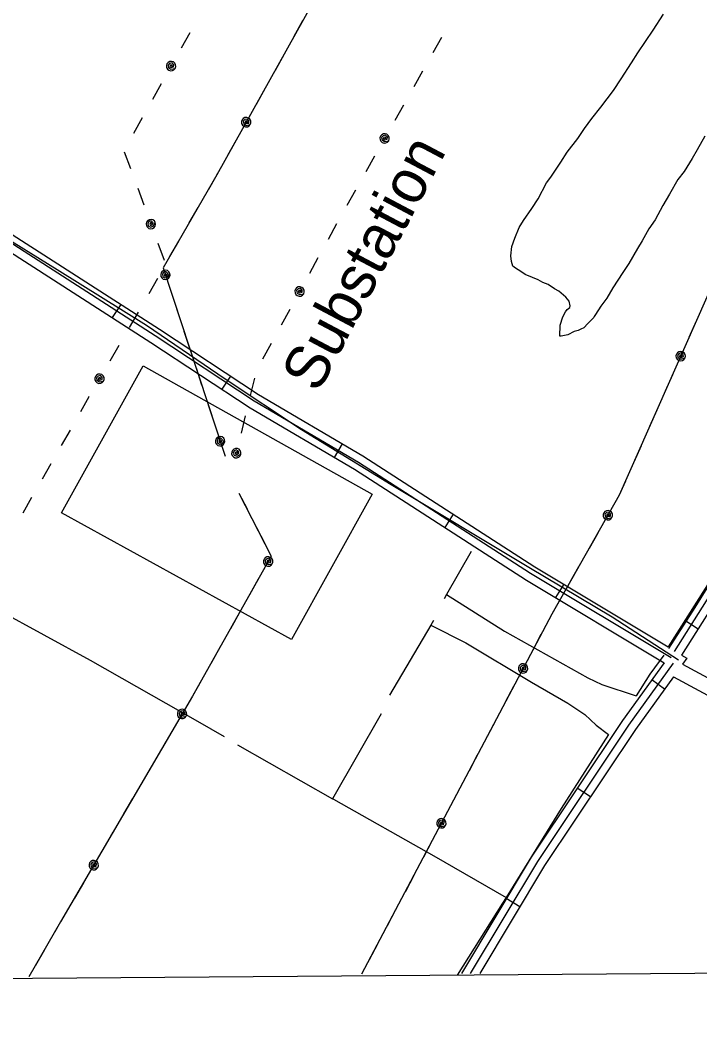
# Model space of a CAD drawing. Extents: x 3535183 to 3573198, y 534952 to 560562.
# Drawn here: x 3551055 to 3552352, y 540353 to 542269 of the extents above; entities that cross this region are included whole.
import ezdxf

# ---------------------------------------------------------------- set-up
doc = ezdxf.new("R2010")
doc.units = 0
for name, color, linetype in [('V-DTCH-CNTR', 7, 'Continuous'), ('V-GRID-FRAM', 7, 'Continuous'), ('V-ROAD-CNTR', 7, 'Continuous'), ('V-SITE-OTLN', 7, 'Continuous'), ('V-SITE-OTLN-IDEN', 7, 'Continuous'), ('V-SITE-VEGE', 7, 'Continuous'), ('V-TOPO-SHOR', 7, 'Continuous'), ('V-UTIL-LINE', 7, 'Continuous')]:
    doc.layers.add(name, color=color, linetype=linetype)

msp = doc.modelspace()

# ---------------------------------------------------------------- linework, layer by layer
at = {"layer": 'V-DTCH-CNTR'}
msp.add_lwpolyline([(3552311.1, 541048.4), (3552184.6, 541130.6), (3552025.6, 541225.3), (3551762.9, 541383.1), (3551592, 541487.8), (3551446.1, 541584.7), (3551296.1, 541686.9), (3551126.2, 541793.3), (3551006.3, 541866.6), (3550875.6, 541949.8), (3550831.4, 541978.4), (3550787.7, 542005.4)], dxfattribs=at)
at = {"layer": 'V-GRID-FRAM'}
msp.add_lwpolyline([(3539245.8, 558535.3), (3570887.5, 558774.6), (3571033, 540592.1), (3539375.4, 540352.7), (3539245.8, 558535.3)], dxfattribs=at)
at = {"layer": 'V-ROAD-CNTR'}
for p, q in [((3551247.2, 541727.2), (3551231, 541702)), ((3551456.7, 541590.4), (3551440.2, 541565.4)), ((3551669.7, 541461.1), (3551654.4, 541435.2)), ((3551881.3, 541326.9), (3551865, 541301.7)), ((3552092.1, 541193.4), (3552076.6, 541167.7)), ((3552348.3, 541107.8), (3552322.9, 541123.8)), ((3552316.8, 541058.1), (3552326.8, 541052.1)), ((3552326.8, 541052.1), (3552318.8, 541041.1)), ((3552284.3, 540993.2), (3552259.9, 541010.7)), ((3552142.8, 540787.7), (3552117.9, 540804.4)), ((3552008.1, 540578.1), (3551982.4, 540593.5))]:
    msp.add_line(p, q, dxfattribs=at)
for points in [[(3552303.4, 541064.8), (3552395.1, 541209.9), (3552544.5, 541444.8), (3552720.5, 541727.3), (3552881, 541989.5), (3553121.8, 542377.6), (3553307.4, 542678.3), (3553572.7, 543100.2), (3553604.9, 543138.1), (3553635.6, 543156.7), (3553696, 543171.6), (3553911.8, 543236.3), (3554010.3, 543265.9), (3554081.2, 543287.1), (3554118.3, 543299.2), (3554151.6, 543315.3), (3554177.7, 543339.4), (3554199.1, 543370.8), (3554286.1, 543503.7), (3554405.1, 543699.7), (3554441.4, 543759.2), (3554471.6, 543804.2)], [(3553451, 542934.8), (3553294.7, 542686.3), (3553109.1, 542385.5), (3552868.2, 541997.3), (3552707.7, 541735.1), (3552531.8, 541452.8), (3552382.4, 541217.9), (3552291.1, 541073.6)], [(3553475.6, 542917.6), (3553320.2, 542670.4), (3553134.6, 542369.7), (3552893.8, 541981.6), (3552733.3, 541719.4), (3552557.2, 541436.9), (3552407.8, 541201.9), (3552316.8, 541058.1)], [(3552297, 541052.6), (3552028.8, 541214), (3551700.7, 541425.3), (3551501.7, 541542.8), (3551313.1, 541667.1), (3550987.1, 541876.4), (3550822.1, 541980.5), (3550776.8, 542012.5)], [(3550806.1, 542010.2), (3550830.4, 541993), (3550995.2, 541889.1), (3551321.2, 541679.7), (3551509.7, 541555.5), (3551708.6, 541438.1), (3552036.8, 541226.7), (3552291.1, 541073.6)], [(3550789.9, 541984.9), (3550813.7, 541968), (3550979.1, 541863.8), (3551304.9, 541654.5), (3551493.8, 541530), (3551692.8, 541412.6), (3552020.9, 541201.3), (3552283.4, 541043.2)], [(3552283.4, 541043.2), (3552204, 540933.1), (3552029.8, 540672.6), (3551896.8, 540450.6)], [(3551914.4, 540450.8), (3552042.4, 540664.5), (3552216.3, 540924.5), (3552301.4, 541042.5)], [(3552318.8, 541041.1), (3552557.8, 540912), (3552832.4, 540737.6), (3552993.6, 540630.8), (3553002.8, 540628), (3553002.1, 540628), (3553002.6, 540628.5), (3553009.5, 540639.8)], [(3552301.2, 541016.6), (3552228.6, 540915.9), (3552055.1, 540656.5), (3551931.9, 540450.9)], [(3552301.2, 541016.6), (3552542.6, 540886.1), (3552816, 540712.5), (3552980.7, 540603.3), (3552999, 540597.8), (3553016.4, 540598.6), (3553027, 540610.8), (3553033.8, 540622)]]:
    msp.add_lwpolyline(points, dxfattribs=at)
at = {"layer": 'V-SITE-OTLN'}
msp.add_lwpolyline([(3551134.1, 541329.3), (3551290, 541610.2), (3551726.4, 541365.4), (3551573.1, 541087.7)], close=True, dxfattribs=at)
at = {"layer": 'V-SITE-VEGE'}
msp.add_lwpolyline([(3552361.1, 542047.7), (3552346.6, 542022.1), (3552336.7, 542005.6), (3552321.5, 541980.9), (3552309.9, 541965.4), (3552293.7, 541937.3), (3552281.1, 541915.9), (3552266.6, 541888.6), (3552254.1, 541871.4), (3552241.4, 541848.3), (3552232.4, 541833.5), (3552216.2, 541805.4), (3552204.6, 541788.2), (3552185.8, 541758.5), (3552174.1, 541738.8), (3552162.6, 541724), (3552152.7, 541707.5), (3552150, 541704.3), (3552149.1, 541701.8), (3552137.7, 541690.4), (3552130.6, 541682.2), (3552124.7, 541679.9), (3552119.5, 541677.6), (3552111.8, 541675.4), (3552099.8, 541669.1), (3552087.1, 541666.2), (3552084.5, 541666.3), (3552085.3, 541687.3), (3552090.1, 541703.2), (3552095.6, 541713.1), (3552098.3, 541717.2), (3552103.5, 541721.2), (3552104.4, 541724.5), (3552102.2, 541733), (3552095.8, 541740.9), (3552082.7, 541752.3), (3552074.5, 541756.9), (3552062.1, 541764.9), (3552052.2, 541768.7), (3552043.1, 541774.1), (3552032.3, 541778.7), (3552018.2, 541784.3), (3552010, 541789.6), (3552000.1, 541795.9), (3551995.2, 541800.3), (3551992.2, 541808.9), (3551990.9, 541819.9), (3551993.3, 541837.5), (3551998.9, 541853.3), (3552007.3, 541874), (3552015.4, 541887.2), (3552031.4, 541910.2), (3552043.1, 541928.3), (3552059.4, 541958.8), (3552067.4, 541969.5), (3552086.2, 541998.3), (3552098.7, 542017.2), (3552119, 542043.4), (3552131.6, 542062.3), (3552145.8, 542082), (3552162.6, 542103.3), (3552186.6, 542135.2), (3552201.7, 542157.4), (3552221.4, 542187.8), (3552233.1, 542206.8), (3552262.6, 542250.3), (3552282.3, 542280.8)], dxfattribs=at)
at = {"layer": 'V-TOPO-SHOR'}
msp.add_line((3551743.6, 540945.8), (3551651.2, 540784.2), dxfattribs=at)
for points in [[(3553030.6, 542245.1), (3552951.6, 542118.4), (3552873, 541993.5), (3552770.3, 541831.3), (3552650, 541641.1), (3552610.1, 541573.9), (3552562, 541499.2), (3552484.4, 541378.6), (3552341.8, 541149.2), (3552292.1, 541070.4)], [(3550478.9, 541450.4), (3550601.5, 541379.7), (3550817.6, 541254.1), (3551011.7, 541145), (3551189, 541048.7), (3551393.3, 540932.3), (3551444.2, 540902.7)], [(3551915.3, 541255.8), (3551868.5, 541173.4), (3551864.1, 541165.6)], [(3551868.5, 541173.4), (3551979, 541104), (3552138.2, 541014.5), (3552164.7, 541002.2), (3552230.4, 540980.6)], [(3551843.4, 541123.8), (3551838.4, 541115.4), (3551759.7, 540981.7)], [(3551838.4, 541115.4), (3551905, 541081.5), (3552030.8, 541006.3), (3552099.8, 540966.3), (3552132, 540945.1), (3552153.8, 540924.3), (3552177.2, 540906.9)], [(3552282.9, 541057.7), (3552256.1, 541022), (3552230.4, 540980.6)], [(3552177.2, 540906.9), (3552087.2, 540765.8), (3551982.1, 540596), (3551975.1, 540584.8), (3551889.1, 540447.3)], [(3551469.7, 540887), (3551651.2, 540784.2), (3551652.9, 540783.3), (3551844.4, 540675.1), (3551982.1, 540596)]]:
    msp.add_lwpolyline(points, dxfattribs=at)
at = {"layer": 'V-UTIL-LINE'}
for points in [[(3552208.3, 543370.1), (3551831.7, 542694), (3551430.6, 541974.5), (3551327.9, 541797.1), (3551446.1, 541437.4)], [(3552764.1, 542685.9), (3552564.5, 542186.9), (3552362.1, 541735.1), (3552197.8, 541363.1), (3552069.3, 541136.5), (3551706.5, 540449.2)], [(3551594.1, 542267.7), (3551577.5, 542238)], [(3551378.8, 542245.4), (3551362.2, 542215.7)], [(3551858.9, 542236.3), (3551842.2, 542206.7)], [(3551558, 542203), (3551541.5, 542173.3)], [(3551343.2, 542181.7), (3551346, 542181.9), (3551344.5, 542183.7), (3551341.8, 542183.4), (3551340.7, 542180.7), (3551343.5, 542178.9), (3551348.1, 542180), (3551348.4, 542184.3), (3551345, 542187.7), (3551340.5, 542186.7), (3551337.5, 542183.4), (3551338.4, 542178.6), (3551343, 542175.6), (3551351, 542177.3), (3551352.1, 542180.6), (3551351.8, 542184.1), (3551350.2, 542187.2), (3551347.6, 542189.5), (3551344.2, 542190.6), (3551340.7, 542190.3), (3551337.6, 542188.7), (3551335.3, 542186), (3551334.2, 542182.7), (3551334.5, 542179.2), (3551336.1, 542176.1), (3551338.8, 542173.8), (3551342.1, 542172.7), (3551345.6, 542173), (3551348.7, 542174.6), (3551351, 542177.3)], [(3551822.6, 542171.8), (3551805.9, 542142.2)], [(3551324.1, 542147.6), (3551307.6, 542117.9)], [(3551522, 542138.4), (3551505.4, 542108.7)], [(3551786.2, 542107.3), (3551769.6, 542077.7)], [(3551288, 542083), (3551271.5, 542053.3)], [(3551486.5, 542074.6), (3551489.3, 542074.9), (3551487.8, 542076.7), (3551485.1, 542076.3), (3551483.9, 542073.6), (3551486.8, 542071.9), (3551491.4, 542073), (3551491.7, 542077.3), (3551488.2, 542080.7), (3551483.8, 542079.7), (3551480.8, 542076.3), (3551481.7, 542071.6), (3551486.3, 542068.6), (3551494.3, 542070.3), (3551495.4, 542073.6), (3551495.1, 542077.1), (3551493.5, 542080.2), (3551490.8, 542082.5), (3551487.5, 542083.6), (3551484, 542083.3), (3551480.9, 542081.7), (3551478.6, 542079), (3551477.5, 542075.7), (3551477.8, 542072.2), (3551479.4, 542069.1), (3551482.1, 542066.8), (3551485.4, 542065.7), (3551488.9, 542066), (3551492, 542067.6), (3551494.3, 542070.3)], [(3551750.4, 542043.7), (3551753.3, 542044), (3551751.8, 542045.8), (3551749, 542045.4), (3551747.9, 542042.7), (3551750.8, 542040.9), (3551755.3, 542042.1), (3551755.7, 542046.3), (3551752.2, 542049.8), (3551747.8, 542048.8), (3551744.8, 542045.4), (3551745.6, 542040.7), (3551750.3, 542037.7), (3551758.3, 542039.3), (3551759.4, 542042.6), (3551759.1, 542046.1), (3551757.5, 542049.3), (3551754.8, 542051.6), (3551751.5, 542052.7), (3551748, 542052.4), (3551744.9, 542050.8), (3551742.6, 542048.1), (3551741.5, 542044.8), (3551741.7, 542041.3), (3551743.3, 542038.2), (3551746, 542035.9), (3551749.3, 542034.8), (3551752.8, 542035.1), (3551756, 542036.6), (3551758.3, 542039.3)], [(3551467.5, 542040.6), (3551450.9, 542010.9)], [(3551254, 542018.3), (3551265.7, 541986.3)], [(3551731.3, 542009.7), (3551714.6, 541980.1)], [(3551431.4, 541975.9), (3551430.6, 541974.5), (3551414.4, 541946.5)], [(3551279.5, 541948.8), (3551291.2, 541916.9)], [(3551695, 541945.3), (3551678.3, 541915.6)], [(3551394.4, 541911.9), (3551377.3, 541882.5)], [(3551304.6, 541880.3), (3551306.3, 541882.6), (3551304, 541882.6), (3551302.5, 541880.3), (3551303.8, 541877.7), (3551307, 541878.7), (3551309.1, 541882.9), (3551306.1, 541886), (3551301.2, 541885.6), (3551299.1, 541881.5), (3551299.7, 541877.1), (3551303.9, 541874.6), (3551309.1, 541876.2), (3551313.1, 541883.4), (3551311.3, 541886.4), (3551308.4, 541888.4), (3551305, 541889.2), (3551301.5, 541888.7), (3551298.6, 541886.9), (3551296.5, 541884), (3551295.7, 541880.6), (3551296.2, 541877.2), (3551298, 541874.2), (3551300.9, 541872.1), (3551304.3, 541871.3), (3551307.8, 541871.8), (3551310.7, 541873.6), (3551312.8, 541876.5), (3551313.6, 541879.9), (3551313.1, 541883.4)], [(3551658.9, 541880.7), (3551642.5, 541850.9)], [(3551318.1, 541843.6), (3551329.8, 541811.7)], [(3551357.3, 541847.8), (3551340.3, 541818.4)], [(3551623.3, 541815.8), (3551607, 541786)], [(3551332.4, 541783.5), (3551334.1, 541785.7), (3551331.8, 541785.8), (3551330.2, 541783.6), (3551331.4, 541780.9), (3551334.7, 541781.8), (3551336.9, 541786), (3551334, 541789.1), (3551329.2, 541788.9), (3551326.9, 541784.9), (3551327.3, 541780.4), (3551331.4, 541777.9), (3551336.7, 541779.3), (3551340.9, 541786.3), (3551339.2, 541789.3), (3551336.5, 541791.5), (3551333.1, 541792.4), (3551329.6, 541792), (3551326.5, 541790.3), (3551324.4, 541787.5), (3551323.4, 541784.1), (3551323.8, 541780.6), (3551325.6, 541777.6), (3551328.3, 541775.4), (3551331.7, 541774.5), (3551335.2, 541774.9), (3551338.3, 541776.6), (3551340.4, 541779.4), (3551341.4, 541782.8), (3551340.9, 541786.3)], [(3551317.6, 541776.4), (3551300.5, 541747)], [(3551588.2, 541751.8), (3551591.1, 541752.1), (3551589.6, 541753.8), (3551586.8, 541753.5), (3551585.7, 541750.7), (3551588.6, 541749), (3551593.2, 541750.2), (3551593.5, 541754.4), (3551590, 541757.8), (3551585.5, 541756.8), (3551582.6, 541753.4), (3551583.5, 541748.7), (3551588.1, 541745.7), (3551596.1, 541747.4), (3551597.2, 541750.8), (3551596.9, 541754.3), (3551595.2, 541757.4), (3551592.6, 541759.6), (3551589.2, 541760.7), (3551585.7, 541760.4), (3551582.6, 541758.8), (3551580.3, 541756.1), (3551579.3, 541752.7), (3551579.6, 541749.2), (3551581.2, 541746.1), (3551583.9, 541743.9), (3551587.3, 541742.8), (3551590.8, 541743.1), (3551593.9, 541744.7), (3551596.1, 541747.4)], [(3551344.6, 541746.4), (3551355.2, 541714.1)], [(3551280.4, 541712.4), (3551263.4, 541683)], [(3551569.5, 541717.6), (3551553.2, 541687.7)], [(3552344.5, 541695.3), (3552330.8, 541664.2)], [(3551367.7, 541676.1), (3551378.3, 541643.8)], [(3551243.3, 541648.4), (3551226.2, 541619)], [(3551534, 541652.6), (3551517.6, 541622.8)], [(3552315, 541628.5), (3552317.8, 541629.1), (3552316.2, 541630.7), (3552313.5, 541630.1), (3552312.6, 541627.3), (3552315.7, 541625.8), (3552320.1, 541627.4), (3552320, 541631.6), (3552316.2, 541634.7), (3552311.9, 541633.3), (3552309.2, 541629.7), (3552310.5, 541625), (3552315.4, 541622.5), (3552323.3, 541624.9), (3552324, 541628.3), (3552323.4, 541631.8), (3552321.5, 541634.7), (3552318.7, 541636.7), (3552315.2, 541637.5), (3552311.8, 541636.9), (3552308.8, 541635), (3552306.8, 541632.1), (3552306, 541628.7), (3552306.6, 541625.3), (3552308.5, 541622.3), (3552311.4, 541620.3), (3552314.8, 541619.5), (3552318.3, 541620.1), (3552321.2, 541622), (3552323.3, 541624.9)], [(3551206.6, 541585.3), (3551209.5, 541585.5), (3551208, 541587.3), (3551205.3, 541587), (3551204.1, 541584.4), (3551207, 541582.5), (3551211.5, 541583.6), (3551211.9, 541587.8), (3551208.5, 541591.3), (3551204.1, 541590.4), (3551201, 541587.1), (3551201.8, 541582.3), (3551206.4, 541579.3), (3551214.4, 541580.8), (3551215.6, 541584.1), (3551215.3, 541587.6), (3551213.8, 541590.8), (3551211.2, 541593.1), (3551207.8, 541594.2), (3551204.3, 541594), (3551201.2, 541592.4), (3551198.9, 541589.8), (3551197.7, 541586.5), (3551197.9, 541583), (3551199.5, 541579.8), (3551202.1, 541577.5), (3551205.4, 541576.4), (3551209, 541576.6), (3551212.1, 541578.1), (3551214.4, 541580.8)], [(3551390.8, 541605.8), (3551401.4, 541573.5)], [(3552299.3, 541592.8), (3552285.5, 541561.7)], [(3551502.2, 541586.3), (3551494.2, 541553.2)], [(3551187.1, 541551.6), (3551186.5, 541550.5), (3551170.2, 541522)], [(3551413.9, 541535.5), (3551424.5, 541503.2)], [(3551484.7, 541514.4), (3551476.7, 541481.3)], [(3552269.4, 541525.1), (3552255.6, 541494)], [(3551150.5, 541487.2), (3551133.7, 541457.7)], [(3551436.6, 541466.1), (3551438.4, 541468.4), (3551436.1, 541468.5), (3551434.5, 541466.3), (3551435.7, 541463.6), (3551438.9, 541464.5), (3551441.2, 541468.7), (3551438.3, 541471.8), (3551433.4, 541471.6), (3551431.1, 541467.6), (3551431.6, 541463.1), (3551435.7, 541460.6), (3551441, 541462), (3551445.2, 541468.9), (3551443.5, 541472), (3551440.7, 541474.2), (3551437.3, 541475.1), (3551433.8, 541474.7), (3551430.8, 541473), (3551428.6, 541470.2), (3551427.7, 541466.8), (3551428.1, 541463.3), (3551429.8, 541460.3), (3551432.6, 541458.1), (3551436, 541457.2), (3551439.5, 541457.6), (3551442.5, 541459.3), (3551444.7, 541462.1), (3551445.6, 541465.5), (3551445.2, 541468.9)], [(3552239.5, 541457.5), (3552225.7, 541426.4)], [(3551467.5, 541443.4), (3551470.2, 541444.5), (3551468.3, 541445.8), (3551465.7, 541444.7), (3551465.4, 541441.8), (3551468.6, 541440.8), (3551472.7, 541443.2), (3551471.9, 541447.4), (3551467.6, 541449.7), (3551463.6, 541447.6), (3551461.6, 541443.5), (3551463.7, 541439.2), (3551469, 541437.6), (3551476.3, 541441.3), (3551476.4, 541444.8), (3551475.2, 541448.1), (3551472.8, 541450.7), (3551469.6, 541452.2), (3551466.1, 541452.3), (3551462.8, 541451.1), (3551460.2, 541448.7), (3551458.8, 541445.5), (3551458.6, 541442), (3551459.8, 541438.7), (3551462.2, 541436.2), (3551465.4, 541434.7), (3551468.9, 541434.5), (3551472.2, 541435.7), (3551474.8, 541438.1), (3551476.3, 541441.3)], [(3551113.9, 541422.9), (3551097.1, 541393.4)], [(3552209.6, 541389.8), (3552197.8, 541363.1), (3552195.4, 541358.9)], [(3551077.3, 541358.6), (3551060.5, 541329.1)], [(3551472.5, 541367.2), (3551534.2, 541247.1), (3551384, 540979.9), (3551132.6, 540549.6), (3551072.1, 540444.4)], [(3551472.5, 541367.2), (3551488, 541337)], [(3552176.2, 541325), (3552179, 541325.2), (3552177.5, 541327), (3552174.8, 541326.7), (3552173.7, 541324), (3552176.5, 541322.2), (3552181.1, 541323.3), (3552181.4, 541327.6), (3552178, 541331), (3552173.5, 541330), (3552170.5, 541326.7), (3552171.4, 541321.9), (3552176, 541318.9), (3552184, 541320.5), (3552185.1, 541323.8), (3552184.8, 541327.4), (3552183.3, 541330.5), (3552180.6, 541332.8), (3552177.3, 541333.9), (3552173.8, 541333.6), (3552170.6, 541332), (3552168.3, 541329.4), (3552167.2, 541326.1), (3552167.5, 541322.6), (3552169.1, 541319.4), (3552171.7, 541317.1), (3552175.1, 541316), (3552178.6, 541316.3), (3552181.7, 541317.9), (3552184, 541320.5)], [(3551506.3, 541301.4), (3551521.8, 541271.2)], [(3552156.9, 541291), (3552140.2, 541261.4)], [(3551528.3, 541236.7), (3551531.2, 541237), (3551529.7, 541238.7), (3551526.9, 541238.4), (3551525.8, 541235.7), (3551528.7, 541233.9), (3551533.2, 541235.1), (3551533.6, 541239.3), (3551530.1, 541242.7), (3551525.7, 541241.7), (3551522.7, 541238.4), (3551523.5, 541233.6), (3551528.2, 541230.7), (3551536.2, 541232.3), (3551537.3, 541235.6), (3551537, 541239.1), (3551535.4, 541242.3), (3551532.7, 541244.5), (3551529.4, 541245.6), (3551525.9, 541245.4), (3551522.8, 541243.8), (3551520.5, 541241.1), (3551519.4, 541237.8), (3551519.7, 541234.3), (3551521.2, 541231.1), (3551523.9, 541228.8), (3551527.2, 541227.8), (3551530.7, 541228), (3551533.9, 541229.6), (3551536.2, 541232.3)], [(3552120.4, 541226.7), (3552103.7, 541197.1)], [(3551509.2, 541202.7), (3551492.6, 541173)], [(3552084, 541162.3), (3552069.3, 541136.5), (3552067.3, 541132.6)], [(3551473, 541138.2), (3551456.3, 541108.5)], [(3552048.6, 541097.3), (3552032.8, 541067.2)], [(3551436.7, 541073.7), (3551420, 541044)], [(3552014.5, 541032.7), (3552017.4, 541033), (3552015.9, 541034.8), (3552013.1, 541034.4), (3552012.1, 541031.7), (3552015, 541029.9), (3552019.5, 541031.2), (3552019.7, 541035.5), (3552016.2, 541038.8), (3552011.8, 541037.7), (3552008.9, 541034.3), (3552009.8, 541029.5), (3552014.6, 541026.7), (3552022.5, 541028.5), (3552023.5, 541031.9), (3552023.1, 541035.4), (3552021.5, 541038.4), (3552018.7, 541040.7), (3552015.4, 541041.7), (3552011.9, 541041.3), (3552008.8, 541039.6), (3552006.6, 541036.9), (3552005.6, 541033.5), (3552005.9, 541030), (3552007.6, 541027), (3552010.3, 541024.7), (3552013.7, 541023.7), (3552017.2, 541024.1), (3552020.3, 541025.8), (3552022.5, 541028.5)], [(3551400.5, 541009.2), (3551384, 540979.9), (3551383.8, 540979.5)], [(3551996.3, 540998.2), (3551980.5, 540968.1)], [(3551364.1, 540945.8), (3551367, 540946.1), (3551365.5, 540947.9), (3551362.8, 540947.6), (3551361.6, 540944.9), (3551364.4, 540943.1), (3551369, 540944.1), (3551369.4, 540948.4), (3551366, 540951.9), (3551361.5, 540950.9), (3551358.5, 540947.6), (3551359.3, 540942.9), (3551363.9, 540939.8), (3551371.9, 540941.3), (3551373, 540944.6), (3551372.8, 540948.1), (3551371.3, 540951.3), (3551368.7, 540953.6), (3551365.3, 540954.8), (3551361.8, 540954.6), (3551358.7, 540953), (3551356.3, 540950.4), (3551355.2, 540947.1), (3551355.4, 540943.6), (3551356.9, 540940.4), (3551359.6, 540938.1), (3551362.9, 540936.9), (3551366.4, 540937.1), (3551369.6, 540938.7), (3551371.9, 540941.3)], [(3551961.8, 540932.8), (3551945.9, 540902.7)], [(3551344.4, 540912.2), (3551327.3, 540882.8)], [(3551927.2, 540867.3), (3551911.4, 540837.3)], [(3551307.1, 540848.3), (3551290, 540818.9)], [(3551892.7, 540801.9), (3551876.8, 540771.8)], [(3551269.8, 540784.4), (3551252.6, 540755)], [(3551858.6, 540737.3), (3551861.5, 540737.7), (3551859.9, 540739.4), (3551857.2, 540739), (3551856.1, 540736.3), (3551859.1, 540734.6), (3551863.6, 540735.8), (3551863.8, 540740.1), (3551860.3, 540743.4), (3551855.8, 540742.3), (3551852.9, 540738.9), (3551853.9, 540734.2), (3551858.6, 540731.3), (3551866.6, 540733.1), (3551867.6, 540736.5), (3551867.2, 540740), (3551865.5, 540743.1), (3551862.8, 540745.3), (3551859.5, 540746.3), (3551856, 540745.9), (3551852.9, 540744.3), (3551850.7, 540741.5), (3551849.7, 540738.2), (3551850, 540734.7), (3551851.7, 540731.6), (3551854.4, 540729.4), (3551857.8, 540728.4), (3551861.3, 540728.7), (3551864.4, 540730.4), (3551866.6, 540733.1)], [(3551232.4, 540720.5), (3551215.3, 540691.1)], [(3551840.4, 540702.9), (3551824.5, 540672.8)], [(3551195.6, 540657.5), (3551198.5, 540657.7), (3551197, 540659.5), (3551194.3, 540659.2), (3551193.1, 540656.5), (3551195.9, 540654.7), (3551200.5, 540655.8), (3551200.9, 540660), (3551197.5, 540663.5), (3551193, 540662.6), (3551190, 540659.3), (3551190.8, 540654.5), (3551195.4, 540651.5), (3551203.4, 540652.9), (3551204.5, 540656.2), (3551204.3, 540659.8), (3551202.8, 540662.9), (3551200.1, 540665.2), (3551196.8, 540666.4), (3551193.3, 540666.2), (3551190.2, 540664.6), (3551187.8, 540662), (3551186.7, 540658.7), (3551186.9, 540655.2), (3551188.4, 540652), (3551191.1, 540649.7), (3551194.4, 540648.6), (3551197.9, 540648.8), (3551201, 540650.3), (3551203.4, 540652.9)], [(3551805.9, 540637.4), (3551790, 540607.3)], [(3551175.9, 540623.8), (3551158.8, 540594.4)], [(3551771.3, 540572), (3551755.4, 540541.9)], [(3551138.6, 540559.9), (3551132.6, 540549.6), (3551121.6, 540530.5)], [(3551101.7, 540495.8), (3551084.7, 540466.3)], [(3551736.8, 540506.5), (3551720.9, 540476.5)]]:
    msp.add_lwpolyline(points, dxfattribs=at)

# ---------------------------------------------------------------- texts
at = {"layer": 'V-SITE-OTLN-IDEN'}
msp.add_text('Substation', height=83, rotation=62.0896, dxfattribs=at).set_placement((3551623.5, 541555.9))

doc.saveas('drawing.dxf')
